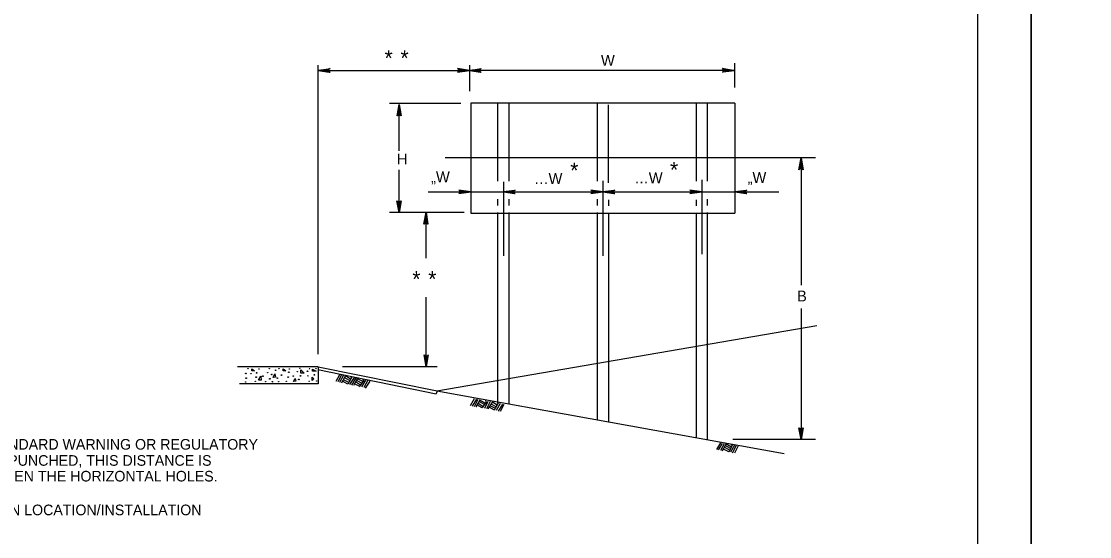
# Model space of a CAD drawing. Extents: x 644358 to 648627, y 294594 to 295782.
# Drawn here: x 645754.7 to 646056.9, y 294889.9 to 295035.6 of the extents above; entities that cross this region are included whole.
import ezdxf

# ---------------------------------------------------------------- set-up
doc = ezdxf.new("R2010")
doc.units = 0
for name, color, linetype in [('1', 7, 'Continuous'), ('2', 7, 'Continuous'), ('3', 7, 'Continuous'), ('4', 7, 'Continuous'), ('PLT-BNDY', 7, 'Continuous')]:
    doc.layers.add(name, color=color, linetype=linetype)

msp = doc.modelspace()

# ---------------------------------------------------------------- linework, layer by layer
at = {"layer": '1'}
msp.add_line((646025.31, 294608.63), (646025.31, 295172.63), dxfattribs=at)
for points in [[(645819.94, 294936.74), (645819.94, 294937.36), (645820.69, 294936.74)], [(645828.81, 294936.74), (645828.81, 294937.36), (645829.56, 294936.74)], [(645833.81, 294936.11), (645833.81, 294936.99), (645834.69, 294936.11)], [(645837.06, 294936.61), (645837.06, 294937.24), (645838.06, 294936.61)], [(645822.44, 294935.24), (645822.56, 294934.11), (645821.81, 294934.11)], [(645826.44, 294935.86), (645826.56, 294934.99), (645825.94, 294934.86)], [(645832.19, 294934.61), (645832.31, 294933.86), (645831.69, 294933.74)], [(645836.94, 294933.99), (645836.94, 294934.99), (645837.44, 294934.49)]]:
    msp.add_lwpolyline(points, close=True, dxfattribs=at)
for centre, radius in [((645818.85, 294937.34), 0.056), ((645821.95, 294937.25), 0.056), ((645824.89, 294937.37), 0.056), ((645826.64, 294936.91), 0.0979), ((645827.62, 294937.34), 0.056), ((645830.55, 294937.3), 0.056), ((645832.76, 294936.55), 0.056), ((645833.49, 294937.42), 0.056), ((645835.66, 294936.61), 0.0979), ((645836.22, 294937.39), 0.056), ((645838.06, 294937.36), 0.056), ((645818.2, 294936.03), 0.0979), ((645818.16, 294933.61), 0.056), ((645818.32, 294934.67), 0.0979), ((645819.68, 294935.92), 0.056), ((645820.87, 294933.81), 0.056), ((645821.13, 294934.94), 0.0979), ((645821.27, 294936.19), 0.0979), ((645823.02, 294935.22), 0.0979), ((645823.85, 294933.66), 0.056), ((645824.38, 294936.23), 0.056), ((645824.99, 294934.48), 0.0979), ((645825.52, 294935.7), 0.0979), ((645825.72, 294933.66), 0.0979), ((645827.1, 294934.67), 0.0979), ((645827.53, 294933.69), 0.056), ((645828.3, 294935.56), 0.0979), ((645829.65, 294933.81), 0.056), ((645830.2, 294934.99), 0.0979), ((645830.39, 294936.34), 0.0979), ((645831.62, 294935.27), 0.0979), ((645833.22, 294934.33), 0.0979), ((645833.67, 294935.3), 0.0979), ((645835.78, 294935.33), 0.056), ((645836.13, 294933.74), 0.056), ((645837.59, 294935.63), 0.0979), ((645838.24, 294933.86), 0.056)]:
    msp.add_circle(centre, radius, dxfattribs=at)
at = {"layer": '2'}
for p, q in [((645881.81, 295012.49), (645881.81, 294981.36)), ((645956.56, 295012.49), (645881.81, 295012.49)), ((645889.44, 295012.49), (645889.44, 294990.4)), ((645892.56, 295012.49), (645892.56, 294990.4)), ((645917.56, 295012.49), (645917.56, 294990.4)), ((645945.56, 295012.49), (645945.56, 294990.4)), ((645948.69, 295012.49), (645948.69, 294990.4)), ((645956.56, 295012.49), (645956.56, 294981.36)), ((645920.69, 295011.99), (645920.69, 294989.9)), ((645891.06, 294990.24), (645891.06, 294969.24)), ((645919.19, 294990.49), (645919.19, 294969.24)), ((645947.19, 294990.74), (645947.19, 294969.74)), ((645869.81, 294987.36), (645881.81, 294987.36)), ((645881.81, 294987.36), (645891.06, 294987.36)), ((645889.44, 294985.26), (645889.44, 294983.51)), ((645891.06, 294987.36), (645919.19, 294987.36)), ((645892.56, 294985.26), (645892.56, 294983.51)), ((645917.56, 294985.26), (645917.56, 294983.51)), ((645919.19, 294987.36), (645947.19, 294987.36)), ((645920.81, 294985.13), (645920.81, 294983.39)), ((645945.56, 294985.13), (645945.56, 294983.39)), ((645947.19, 294987.36), (645956.56, 294987.36)), ((645948.69, 294985.26), (645948.69, 294983.51)), ((645956.56, 294987.36), (645969.01, 294987.36)), ((645881.81, 294981.36), (645956.56, 294981.36)), ((645889.44, 294981.49), (645889.44, 294927.99)), ((645892.56, 294981.49), (645892.56, 294927.36)), ((645917.56, 294981.49), (645917.56, 294922.92)), ((645920.81, 294981.36), (645920.81, 294922.33)), ((645945.56, 294981.36), (645945.56, 294917.86)), ((645948.69, 294981.49), (645948.69, 294917.36)), ((645872.19, 294931.11), (645979.69, 294949.61)), ((645838.69, 294937.86), (645815.81, 294937.86)), ((645838.56, 294937.11), (645872.06, 294930.24)), ((645838.69, 294937.86), (645872.31, 294931.11)), ((645838.69, 294937.86), (645838.69, 294933.11)), ((645844.69, 294935.61), (645843.69, 294933.74)), ((645845.31, 294935.61), (645844.19, 294933.61)), ((645845.81, 294935.49), (645844.69, 294933.49)), ((645846.44, 294935.36), (645845.31, 294933.36)), ((645847.06, 294932.99), (645845.56, 294933.86)), ((645847.31, 294933.49), (645845.81, 294934.24)), ((645847.56, 294933.99), (645846.06, 294934.86)), ((645847.81, 294934.36), (645846.44, 294935.36)), ((645848.19, 294934.99), (645847.06, 294932.99)), ((645848.81, 294934.86), (645847.56, 294932.86)), ((645848.19, 294934.86), (645847.81, 294934.99)), ((645849.31, 294934.74), (645848.06, 294932.74)), ((645849.81, 294934.61), (645848.69, 294932.61)), ((645850.69, 294932.74), (645849.19, 294933.61)), ((645850.94, 294933.24), (645849.44, 294934.11)), ((645851.31, 294933.74), (645849.81, 294934.49)), ((645851.56, 294934.11), (645850.31, 294932.24)), ((645852.06, 294934.11), (645850.94, 294932.24)), ((645851.56, 294934.11), (645851.31, 294934.24)), ((645852.69, 294934.11), (645851.56, 294931.99)), ((645853.31, 294933.86), (645851.94, 294931.86)), ((645838.69, 294933.11), (645816.44, 294933.11)), ((645845.56, 294933.36), (645845.31, 294933.49)), ((645850.44, 294932.36), (645848.94, 294933.11)), ((645872.31, 294931.11), (645872.06, 294930.24)), ((645872.19, 294931.11), (645970.44, 294913.36)), ((645882.81, 294928.86), (645881.69, 294926.86)), ((645883.44, 294928.74), (645882.19, 294926.74)), ((645883.81, 294928.61), (645882.81, 294926.61)), ((645884.44, 294928.49), (645883.31, 294926.61)), ((645885.31, 294926.61), (645883.81, 294927.61)), ((645885.69, 294927.24), (645884.19, 294928.11)), ((645885.94, 294927.61), (645884.44, 294928.49)), ((645886.31, 294928.11), (645885.06, 294926.24)), ((645886.69, 294928.11), (645885.69, 294926.11)), ((645886.19, 294928.11), (645885.94, 294928.24)), ((645887.31, 294928.11), (645886.31, 294925.99)), ((645887.94, 294927.99), (645886.69, 294925.99)), ((645889.31, 294926.99), (645887.94, 294927.86)), ((645889.56, 294927.61), (645888.44, 294925.61)), ((645890.19, 294927.49), (645889.06, 294925.49)), ((645889.56, 294927.49), (645889.31, 294927.74)), ((645883.56, 294926.61), (645883.44, 294926.61)), ((645885.06, 294926.24), (645883.56, 294927.11)), ((645888.56, 294925.61), (645887.06, 294926.49)), ((645888.81, 294926.11), (645887.31, 294926.86)), ((645889.06, 294926.61), (645887.56, 294927.36)), ((645890.81, 294927.36), (645889.56, 294925.36)), ((645891.19, 294927.24), (645890.19, 294925.24)), ((645952.44, 294916.36), (645951.31, 294914.49)), ((645952.94, 294916.24), (645951.81, 294914.36)), ((645953.56, 294916.11), (645952.44, 294914.24)), ((645954.06, 294916.11), (645952.94, 294914.11)), ((645955.31, 294914.74), (645953.81, 294915.61)), ((645955.44, 294915.24), (645953.94, 294916.11)), ((645955.81, 294915.74), (645954.81, 294913.74)), ((645956.44, 294915.74), (645955.31, 294913.74)), ((645955.81, 294915.74), (645955.44, 294915.86)), ((645956.94, 294915.61), (645955.81, 294913.49)), ((645957.44, 294915.49), (645956.44, 294913.49)), ((645953.19, 294914.11), (645952.94, 294914.24)), ((645954.81, 294913.86), (645953.31, 294914.61)), ((645954.94, 294914.36), (645953.56, 294915.11))]:
    msp.add_line(p, q, dxfattribs=at)
at = {"layer": '4'}
for p, q in [((645838.69, 294941.49), (645838.69, 295023.24)), ((645838.69, 295021.74), (645881.44, 295021.74)), ((645881.44, 295023.24), (645881.44, 295015.86)), ((645956.44, 295021.74), (645881.44, 295021.74)), ((645956.44, 295023.74), (645956.44, 295016.86)), ((645879.06, 295012.36), (645858.87, 295012.36)), ((645861.56, 294998.99), (645861.56, 295012.11)), ((645979.35, 294996.99), (645874.56, 294996.99)), ((645975.26, 294996.99), (645975.26, 294960.99)), ((645861.56, 294981.49), (645861.56, 294993.61)), ((645879.94, 294981.49), (645858.87, 294981.49)), ((645869.19, 294968.61), (645869.19, 294981.74)), ((645869.19, 294937.86), (645869.19, 294957.61)), ((645975.26, 294954.36), (645975.26, 294917.36)), ((645872.31, 294937.86), (645845.56, 294937.86)), ((645979.35, 294917.36), (645955.94, 294917.36))]:
    msp.add_line(p, q, dxfattribs=at)
for points in [[(645841.81, 295021.24), (645841.69, 295021.49), (645838.69, 295021.74), (645841.81, 295021.24), (645842.06, 295021.24), (645838.69, 295021.74), (645841.69, 295021.86), (645841.81, 295022.11), (645838.69, 295021.74), (645842.06, 295022.24), (645841.81, 295022.11)], [(645878.31, 295021.24), (645878.44, 295021.49), (645881.44, 295021.74), (645878.31, 295021.24), (645878.06, 295021.24), (645881.44, 295021.74), (645878.44, 295021.86), (645878.31, 295022.11), (645881.44, 295021.74), (645878.06, 295022.24), (645878.31, 295022.11)], [(645884.56, 295021.24), (645884.44, 295021.49), (645881.44, 295021.74), (645884.56, 295021.24), (645884.81, 295021.24), (645881.44, 295021.74), (645884.44, 295021.86), (645884.56, 295022.11), (645881.44, 295021.74), (645884.81, 295022.24), (645884.56, 295022.11)], [(645953.19, 295022.11), (645953.31, 295021.86), (645956.44, 295021.74), (645953.19, 295022.11), (645953.06, 295022.36), (645956.44, 295021.74), (645953.31, 295021.61), (645953.19, 295021.36), (645956.44, 295021.74), (645953.06, 295021.24), (645953.19, 295021.36)], [(645861.19, 295008.99), (645861.44, 295009.11), (645861.56, 295012.11), (645861.19, 295008.99), (645861.06, 295008.86), (645861.56, 295012.11), (645861.81, 295009.11), (645862.06, 295008.99), (645861.56, 295012.11), (645862.19, 295008.86), (645862.06, 295008.99)], [(645974.88, 294993.86), (645975.13, 294993.99), (645975.26, 294996.99), (645974.88, 294993.86), (645974.63, 294993.61), (645975.26, 294996.99), (645975.38, 294993.99), (645975.63, 294993.86), (645975.26, 294996.99), (645975.88, 294993.61), (645975.63, 294993.86)], [(645878.69, 294986.86), (645878.81, 294987.11), (645881.81, 294987.36), (645878.69, 294986.86), (645878.44, 294986.86), (645881.81, 294987.36), (645878.81, 294987.49), (645878.69, 294987.74), (645881.81, 294987.36), (645878.44, 294987.86), (645878.69, 294987.74)], [(645894.19, 294986.86), (645894.06, 294987.11), (645891.06, 294987.36), (645894.19, 294986.86), (645894.44, 294986.86), (645891.06, 294987.36), (645894.06, 294987.49), (645894.19, 294987.74), (645891.06, 294987.36), (645894.44, 294987.86), (645894.19, 294987.74)], [(645916.06, 294986.86), (645916.19, 294987.11), (645919.19, 294987.36), (645916.06, 294986.86), (645915.81, 294986.86), (645919.19, 294987.36), (645916.19, 294987.49), (645916.06, 294987.74), (645919.19, 294987.36), (645915.81, 294987.86), (645916.06, 294987.74)], [(645922.31, 294986.86), (645922.19, 294987.11), (645919.19, 294987.36), (645922.31, 294986.86), (645922.56, 294986.86), (645919.19, 294987.36), (645922.19, 294987.49), (645922.31, 294987.74), (645919.19, 294987.36), (645922.56, 294987.86), (645922.31, 294987.74)], [(645944.06, 294986.86), (645944.19, 294987.11), (645947.19, 294987.36), (645944.06, 294986.86), (645943.81, 294986.86), (645947.19, 294987.36), (645944.19, 294987.49), (645944.06, 294987.74), (645947.19, 294987.36), (645943.81, 294987.86), (645944.06, 294987.74)], [(645959.69, 294986.86), (645959.56, 294987.11), (645956.56, 294987.36), (645959.69, 294986.86), (645959.94, 294986.86), (645956.56, 294987.36), (645959.56, 294987.49), (645959.69, 294987.74), (645956.56, 294987.36), (645959.94, 294987.86), (645959.69, 294987.74)], [(645861.94, 294984.61), (645861.69, 294984.49), (645861.56, 294981.49), (645861.94, 294984.61), (645862.19, 294984.86), (645861.56, 294981.49), (645861.44, 294984.49), (645861.19, 294984.61), (645861.56, 294981.49), (645860.94, 294984.86), (645861.19, 294984.61)], [(645868.69, 294978.36), (645868.94, 294978.49), (645869.19, 294981.61), (645868.69, 294978.36), (645868.56, 294978.24), (645869.19, 294981.61), (645869.31, 294978.49), (645869.56, 294978.36), (645869.19, 294981.61), (645869.69, 294978.24), (645869.56, 294978.36)], [(645869.69, 294940.99), (645869.44, 294940.86), (645869.19, 294937.86), (645869.69, 294940.99), (645869.81, 294941.24), (645869.19, 294937.86), (645869.06, 294940.86), (645868.81, 294940.99), (645869.19, 294937.86), (645868.69, 294941.24), (645868.81, 294940.99)], [(645975.63, 294920.49), (645975.51, 294920.36), (645975.26, 294917.36), (645975.63, 294920.49), (645975.88, 294920.61), (645975.26, 294917.36), (645975.13, 294920.36), (645974.88, 294920.49), (645975.26, 294917.36), (645974.63, 294920.61), (645974.88, 294920.49)]]:
    msp.add_lwpolyline(points, dxfattribs=at)
at = {"layer": 'PLT-BNDY'}
for points in [[(645199.31, 295187.63), (646040.31, 295187.63), (646040.31, 294593.63), (645199.31, 294593.63)], [(646040.31, 295187.63), (646881.31, 295187.63), (646881.31, 294593.63), (646040.31, 294593.63)]]:
    msp.add_lwpolyline(points, close=True, dxfattribs=at)

# ---------------------------------------------------------------- texts
at = {"layer": '3'}
for s, height, p in [('„W', 3.09, (645870.62, 294990.04)), ('…W', 3.09, (645899.71, 294989.59)), ('…W', 3.09, (645928.06, 294989.76)), ('„W', 3.09, (645960.15, 294989.86)), ('B', 3.09, (645974.13, 294956.36)), ('SEE SHEET 9 FOR SIGN LOCATION/INSTALLATION', 3, (645708.03, 294895.91))]:
    msp.add_text(s, height=height, dxfattribs=at).set_placement(p)
at = {"layer": '4'}
for s, height, p in [('*', 4.45, (645857.44, 295022.99)), ('*', 4.45, (645861.94, 295022.99)), ('W', 3.09, (645918.66, 295023.02)), ('H', 3.09, (645860.94, 294995.11)), ('*', 4.45, (645909.96, 294991.21)), ('*', 4.45, (645938.19, 294991.39)), ('*', 4.45, (645865.31, 294960.49)), ('*', 4.45, (645869.81, 294960.49)), ('WHEN ERECTING STANDARD WARNING OR REGULATORY', 3, (645707.97, 294914.46)), ('SIGNS THAT ARE PREPUNCHED, THIS DISTANCE IS', 3, (645708.2, 294909.9)), ('THE DISTANCE BETWEEN THE HORIZONTAL HOLES.', 3, (645707.91, 294905.45))]:
    msp.add_text(s, height=height, dxfattribs=at).set_placement(p)

doc.saveas('drawing.dxf')
